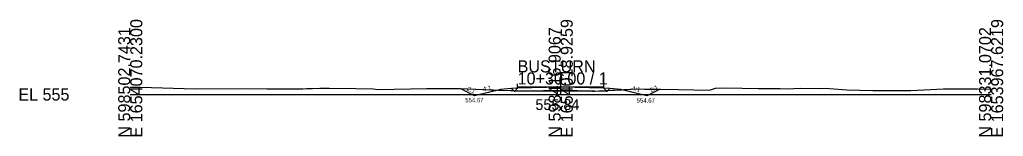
# Model space of a CAD drawing. Extents: x -26 to 1403, y -10 to 2017.
# Drawn here: x -25.7 to 202.8, y 990.3 to 1017.3 of the extents above; entities that cross this region are included whole.
import ezdxf

# ---------------------------------------------------------------- set-up
doc = ezdxf.new("R2010")
doc.units = 0
for name, color, linetype in [('Exist Cross Section Cell', 7, 'Continuous'), ('Exist XS Center Line Elevation Label', 7, 'Continuous'), ('Exist XS Ground Line', 7, 'Continuous'), ('Prop XS Ditch Slope Text', 7, 'Continuous'), ('Prop XS Earthwork Shape', 7, 'Continuous'), ('Prop XS EOT Tick Mark', 7, 'Continuous'), ('Prop XS Finish Grade', 7, 'Continuous'), ('Prop XS Finish Grade Earthwork', 7, 'Continuous'), ('Prop XS Finish Grade Pavement', 7, 'Continuous'), ('Prop XS Pvmt Edge Slope', 7, 'Continuous'), ('Prop XS Subgrade Earthwork', 7, 'Continuous')]:
    doc.layers.add(name, color=color, linetype=linetype)

msp = doc.modelspace()

# ---------------------------------------------------------------- linework, layer by layer
at = {"layer": 'Exist Cross Section Cell'}
for p, q in [((100, 1000), (100, 1005.12)), ((0, 1000), (100, 1000)), ((100, 1000), (200, 1000))]:
    msp.add_line(p, q, dxfattribs=at)
at = {"layer": 'Exist XS Ground Line'}
for p, q in [((0, 1001.7), (0.4, 1001.7)), ((0.4, 1001.7), (1.13, 1001.71)), ((1.13, 1001.71), (2.36, 1001.7)), ((2.36, 1001.7), (15.05, 1001.31)), ((15.05, 1001.31), (26.11, 1001.39)), ((26.11, 1001.39), (31.74, 1001.33)), ((31.74, 1001.33), (35.58, 1001.34)), ((35.58, 1001.34), (40.07, 1001.3)), ((40.07, 1001.3), (40.95, 1001.41)), ((40.95, 1001.41), (42.34, 1001.42)), ((42.34, 1001.42), (44.07, 1001.46)), ((44.07, 1001.46), (46.19, 1001.5)), ((46.19, 1001.5), (52.39, 1001.39)), ((52.39, 1001.39), (56.44, 1001.29)), ((56.44, 1001.29), (57.6, 1001.13)), ((57.6, 1001.13), (68.83, 1001.35)), ((68.83, 1001.35), (74.01, 1001.39)), ((74.01, 1001.39), (74.83, 1001.37)), ((74.83, 1001.37), (76.45, 1001.36)), ((76.45, 1001.36), (90.17, 1000.88)), ((107.37, 1000.76), (117.58, 1001.29)), ((117.58, 1001.29), (119.49, 1001.25)), ((119.49, 1001.25), (127.4, 1001.18)), ((127.4, 1001.18), (134.58, 1001.03)), ((134.58, 1001.03), (136, 1001.44)), ((136, 1001.44), (138.4, 1001.52)), ((138.4, 1001.52), (145.98, 1001.4)), ((145.98, 1001.4), (150.98, 1001.37)), ((150.98, 1001.37), (152.71, 1001.34)), ((152.71, 1001.34), (155.63, 1001.49)), ((155.63, 1001.49), (160.26, 1001.4)), ((160.26, 1001.4), (161.44, 1001.43)), ((161.44, 1001.43), (166.51, 1001.08)), ((166.51, 1001.08), (172.56, 1000.96)), ((181.37, 1000.94), (188.94, 1001.3)), ((188.94, 1001.3), (196.87, 1001.29)), ((196.87, 1001.29), (200, 1001.21)), ((90.17, 1000.88), (98.89, 1000.86)), ((98.89, 1000.86), (100, 1000.84)), ((100, 1000.84), (107.37, 1000.76)), ((172.56, 1000.96), (181.37, 1000.94))]:
    msp.add_line(p, q, dxfattribs=at)
at = {"layer": 'Prop XS Earthwork Shape'}
for points in [[(80, 999.67), (76.65, 1001.35), (85.47, 1001.04)], [(85.47, 1001.04), (89.07, 1000.92), (88.59, 1001.38), (86, 1001.17)], [(111.41, 1001.38), (110.96, 1000.94), (114.24, 1001.11), (114, 1001.17)], [(123.09, 1001.22), (120, 999.67), (114.24, 1001.11), (117.58, 1001.29), (119.49, 1001.25)], [(89.07, 1000.92), (90.17, 1000.88), (95.99, 1000.86), (89.27, 1000.73)], [(95.99, 1000.86), (98.89, 1000.86), (100, 1000.84), (107.37, 1000.76), (107.89, 1000.79), (100, 1000.94)], [(110.73, 1000.73), (107.89, 1000.79), (110.96, 1000.94)]]:
    msp.add_lwpolyline(points, close=True, dxfattribs=at)
at = {"layer": 'Prop XS EOT Tick Mark'}
for p, q in [((90, 1001.49), (90, 1002.49)), ((110, 1001.49), (110, 1002.49))]:
    msp.add_line(p, q, dxfattribs=at)
at = {"layer": 'Prop XS Finish Grade'}
for p, q in [((90, 1001.49), (88.59, 1001.38)), ((111.41, 1001.38), (110, 1001.49))]:
    msp.add_line(p, q, dxfattribs=at)
at = {"layer": 'Prop XS Finish Grade Earthwork'}
for p, q in [((80, 999.67), (76.65, 1001.35)), ((86, 1001.17), (80, 999.67)), ((88.59, 1001.38), (86, 1001.17)), ((114, 1001.17), (111.41, 1001.38)), ((120, 999.67), (114, 1001.17)), ((123.09, 1001.22), (120, 999.67))]:
    msp.add_line(p, q, dxfattribs=at)
at = {"layer": 'Prop XS Finish Grade Pavement'}
for p, q in [((110, 1001.7), (90, 1001.68)), ((100, 1001.69), (90, 1001.49)), ((110, 1001.49), (100, 1001.69))]:
    msp.add_line(p, q, dxfattribs=at)
at = {"layer": 'Prop XS Pvmt Edge Slope'}
for p, q in [((89.27, 1000.73), (90, 1001.49)), ((110.73, 1000.73), (110, 1001.49))]:
    msp.add_line(p, q, dxfattribs=at)
at = {"layer": 'Prop XS Subgrade Earthwork'}
for p, q in [((88.59, 1001.38), (89.27, 1000.73)), ((111.41, 1001.38), (110.73, 1000.73)), ((100, 1000.94), (89.27, 1000.73)), ((110.73, 1000.73), (100, 1000.94))]:
    msp.add_line(p, q, dxfattribs=at)

# ---------------------------------------------------------------- texts
at = {"layer": 'Exist Cross Section Cell'}
for s, p in [('E 1654070.2300', (2.8, 990)), ('E 1654018.9259', (102.8, 990)), ('E 1653967.6219', (202.8, 990)), ('N 598502.7431', (0, 990)), ('N 598416.9067', (100, 990)), ('N 598331.0702', (200, 990))]:
    msp.add_text(s, height=2.8, rotation=90, dxfattribs=at).set_placement(p)
for s, p in [('BUSTURN', (90, 1005.12)), ('10+30.00 / 1', (90, 1002.32)), ('EL 555', (-26, 998.6))]:
    msp.add_text(s, height=2.8, dxfattribs=at).set_placement(p)
at = {"layer": 'Exist XS Center Line Elevation Label'}
msp.add_text('555.84', height=2.5, dxfattribs=at).set_placement((94.13, 996.41))
at = {"layer": 'Prop XS Ditch Slope Text'}
for s, rotation, p in [('2:1', 333.4349, (78.12, 1001)), ('4:1', 14.0362, (82.09, 1000.71)), ('4:1', 345.9638, (116.49, 1001.07)), ('2:1', 26.5651, (121.03, 1000.48))]:
    msp.add_text(s, height=1, rotation=rotation, dxfattribs=at).set_placement(p)
for p in [(77.84, 998.18), (117.66, 998.13)]:
    msp.add_text('554.67', height=1, dxfattribs=at).set_placement(p)

doc.saveas('drawing.dxf')
